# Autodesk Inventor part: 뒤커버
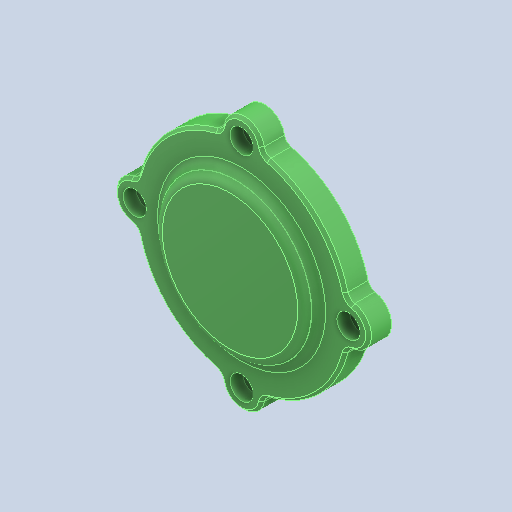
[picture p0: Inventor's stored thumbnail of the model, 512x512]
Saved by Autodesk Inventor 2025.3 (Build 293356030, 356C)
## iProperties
Created: 2025-08
Part Number: 뒤커버
Material: 알루미늄 6061
Document SubType Name: Modeling
Designer: user
Density: 2.71 g/cm^3
Appearance: 기본값
Company: 한국ATC센터
Author: jhkim
Sending System: Autodesk Inventor 2026
Preprocessor: ST-DEVELOPER v20.1
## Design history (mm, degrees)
sketch "스케치1"
  geometry: 1 further point
  constraints: 1 other
feature "솔리드1"
node "솔리드2"
